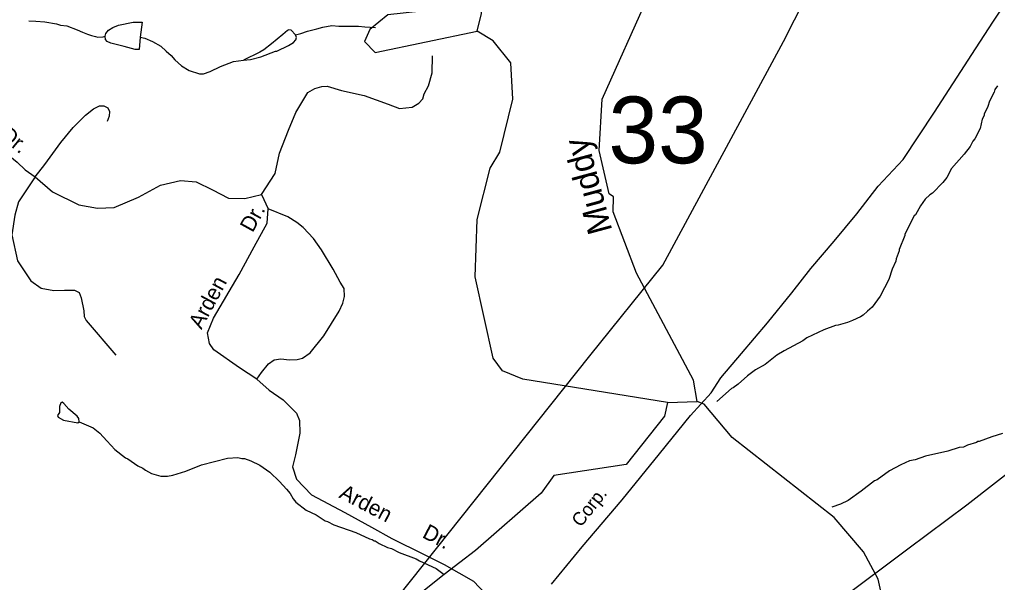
# Model space of a CAD drawing. Extents: x 1547597 to 1699558, y 810033 to 920809.
# Drawn here: x 1595166 to 1601176, y 826362 to 829821 of the extents above; entities that cross this region are included whole.
import ezdxf

# ---------------------------------------------------------------- set-up
doc = ezdxf.new("R2010")
doc.units = 0
for name, color, linetype in [('Exist Boundary Political City Limit New', 7, 'Continuous'), ('Exist Hydrographic Creek Single Shore', 7, 'Continuous'), ('Exist Hydrographic Creek Single Shore Label', 7, 'Continuous'), ('Exist Hydrographic Misc Water Feature', 7, 'Continuous'), ('Exist Hydrographic Pond Under 1500 Sq Ft', 7, 'Continuous'), ('Exist Railroad Mainline', 7, 'Continuous'), ('Exist Railroad Mainline Label', 7, 'Continuous'), ('Exist Road Non-System Type 51', 7, 'Continuous'), ('Exist Road Non-System Type 51 Label', 7, 'Continuous'), ('Exist Road Secondary Structure Standard Bridge Number Label', 7, 'Continuous'), ('Exist Utilities Electrical Transmission Line', 7, 'Continuous'), ('Map Preparation Boundary City Limit Buffer Line', 7, 'Continuous')]:
    doc.layers.add(name, color=color, linetype=linetype)

msp = doc.modelspace()

# ---------------------------------------------------------------- linework, layer by layer
at = {"layer": 'Exist Boundary Political City Limit New'}
msp.add_lwpolyline([(1595159.9, 823742.9), (1596126.5, 824626.4), (1596938.9, 825577.9), (1598671.6, 827755.3), (1599119.8, 828312.6), (1599862.2, 829685.3), (1600674.7, 831289.2), (1600128.4, 831887.3), (1599217.9, 832804.7), (1599067.4, 833015.2), (1598754.8, 833517.5), (1598535.5, 834121.7), (1598377.2, 834572.6), (1598149, 835207), (1597793.5, 835631), (1597451.9, 835864.5), (1596684.8, 836157), (1596268.5, 836512.2)], dxfattribs=at)
at = {"layer": 'Exist Hydrographic Creek Single Shore'}
msp.add_line((1599148.6, 827468.1), (1599331.6, 827474.3), dxfattribs=at)
for points in [[(1599331.6, 827474.3), (1599308.6, 827606), (1598958.6, 828263.1), (1598813.6, 828640.2), (1598815.6, 828732.1), (1598790.6, 828749.1), (1598727.6, 829016.2), (1598747.6, 829330.9), (1599031.6, 829968.6), (1599097, 830143.8), (1599212, 830246.7), (1599453.2, 830408), (1599920.6, 831033.9), (1600066.6, 831316.5), (1600092.7, 831424.3), (1600064.7, 831799.1)], [(1599148.6, 827468.1), (1598258.6, 827610.9), (1598133.6, 827662.7), (1598076.6, 827739.3), (1597966.6, 828240.5), (1597979.6, 828591.5), (1598058.6, 828908.3), (1598118.6, 829005.6), (1598197.7, 829332.2), (1598184.7, 829555.7), (1598077.6, 829689.2), (1597978.6, 829750.3)], [(1599148.6, 827468.1), (1599130.7, 827383.1), (1598893.6, 827085.9), (1598450.6, 827019.4), (1598373, 826911), (1597968.6, 826558.9), (1597775.8, 826410), (1597490.3, 826184.3), (1597347.3, 826111.7), (1596877.3, 825951.8), (1596099.6, 825773.7), (1595674.6, 825788.9), (1595550.7, 825820.9), (1595012.6, 826130.5), (1594738.6, 826218.2), (1594623.6, 826351.8), (1594518.6, 826587), (1594430.6, 826880.9), (1594384.6, 827203.6), (1594403.6, 827380.4), (1594498.6, 827654.3), (1594492.6, 827828.4), (1594348.6, 828264.6)], [(1600488.6, 826055.7), (1600482.7, 826206.8), (1600442.6, 826381.6), (1600353.6, 826550.8), (1600172.6, 826761.3), (1599545.6, 827253.3), (1599373.6, 827457), (1599331.6, 827474.3)]]:
    msp.add_lwpolyline(points, dxfattribs=at)
at = {"layer": 'Exist Hydrographic Misc Water Feature'}
for points in [[(1595223.4, 829812.1), (1595265.9, 829810.9), (1595321.9, 829806.1), (1595393.7, 829795.1), (1595417.6, 829786.8), (1595457.5, 829782.2), (1595521.1, 829757.4), (1595552.9, 829742.9), (1595584.7, 829730.4), (1595608.6, 829722.1), (1595632.5, 829715.8), (1595648.5, 829713.6), (1595680.5, 829715.1), (1595693.5, 829719)], [(1595693.5, 829719), (1595695.7, 829735.2), (1595713.1, 829755.1), (1595739, 829772.3), (1595775.4, 829786.3), (1595864.7, 829805.8), (1595920.2, 829805.6), (1595908.2, 829712.3)], [(1596862.7, 829726.5), (1596836.3, 829755), (1596820.3, 829757.2), (1596812.2, 829753.4), (1596783.9, 829729.7), (1596715.2, 829670.7), (1596666.8, 829635.4), (1596642.6, 829619.7), (1596542, 829571)], [(1596862.7, 829726.5), (1596896, 829734.2), (1596936.2, 829749.6), (1596992.4, 829764.8), (1597030.4, 829774.3), (1597086.5, 829783.5), (1597128.5, 829780.9), (1597248.4, 829781.2), (1597288.4, 829776.7), (1597353.5, 829771.1)], [(1595908.2, 829712.3), (1595900.5, 829636.7), (1595876.4, 829637), (1595810.3, 829655.6), (1595726.6, 829676.3), (1595704.9, 829686.1), (1595694.1, 829698), (1595693.5, 829719)], [(1595908.2, 829712.3), (1595936.2, 829705.6), (1595983.8, 829686.9), (1596035.4, 829658.2), (1596067, 829625.8), (1596098.6, 829599.3), (1596120.2, 829573), (1596161.7, 829536.5), (1596209.3, 829507.8), (1596273, 829486.9), (1596296.9, 829486.6), (1596337.1, 829502), (1596401.5, 829533.1), (1596481.9, 829564), (1596542, 829571)], [(1596542, 829571), (1596586, 829574.5), (1596650.1, 829591.6), (1596738.6, 829626.4), (1596746.6, 829626.3), (1596819, 829661.3), (1596849.3, 829680.8), (1596863.5, 829696.7), (1596867.7, 829710.5), (1596862.7, 829726.5)], [(1601177.1, 829414.6), (1601160.8, 829390.8), (1601156.6, 829374.9), (1601127.9, 829319.3), (1601117.4, 829287.4), (1601094.8, 829239.7), (1601094.6, 829231.8), (1601082.3, 829207.9), (1601069.6, 829152.1), (1601036.7, 829088.6), (1601024.5, 829072.8), (1601008.1, 829041), (1600971.5, 828993.5), (1600894.4, 828906.6), (1600865.6, 828851), (1600841.2, 828819.4), (1600776.3, 828754.3), (1600760.2, 828744.5), (1600731.9, 828716.9), (1600703.3, 828677.3), (1600672.7, 828621.8), (1600664.6, 828613.9), (1600607, 828502.7), (1600606.9, 828494.7), (1600571.8, 828407.2), (1600571.7, 828399.2), (1600553, 828351.5), (1600550.7, 828335.6), (1600530.1, 828287.8), (1600509.3, 828224.2), (1600455.9, 828120.9), (1600407, 828053.6), (1600376.7, 828030), (1600350.4, 828004.4), (1600334.2, 827994.7), (1600285.9, 827971.3), (1600253.8, 827959.8), (1600197.6, 827942.5), (1600181.7, 827940.8), (1600109.3, 827913.8), (1600004.7, 827865.3), (1599980.5, 827847.6), (1599865.7, 827785.2), (1599821.3, 827757.8), (1599748.6, 827700.9), (1599690.1, 827667.7), (1599639.7, 827632.4), (1599583, 827581.2), (1599552.8, 827557.7), (1599542.7, 827553.8), (1599451.9, 827473.1)], [(1595532.8, 827350), (1595529.7, 827370.5), (1595519.6, 827384.4), (1595468.7, 827426.6), (1595437.8, 827461.7), (1595427.5, 827469.3), (1595419.5, 827465.9), (1595411.8, 827443.2), (1595412.7, 827406.1), (1595399.8, 827388), (1595403.2, 827378.3), (1595436, 827360.2), (1595525.3, 827342.7), (1595532.8, 827350)], [(1595532.8, 827350), (1595619.1, 827312.5), (1595659.7, 827278.9), (1595703.7, 827232.2)], [(1595703.7, 827232.2), (1595730, 827202.9), (1595751.8, 827178.7), (1595817, 827127.8), (1595831, 827121.6), (1595892.4, 827078.8), (1595924.2, 827064.3), (1595939.9, 827052.1), (1595977.7, 827031.6), (1596035.4, 827014.8), (1596075.4, 827014.2), (1596107.5, 827021.8), (1596187.8, 827046.7), (1596284.2, 827085.3), (1596444.7, 827125), (1596508.7, 827130.2), (1596532.5, 827123.8), (1596548.5, 827123.6), (1596588.3, 827109.1), (1596644, 827082.3), (1596705.3, 827039.4), (1596764.6, 826982.6), (1596807.8, 826936), (1596829.5, 826907.7), (1596847, 826875.5), (1596864.7, 826855.3), (1596928, 826806.4), (1596989.6, 826777.5), (1597045.1, 826740.8), (1597059, 826736.6), (1597098.7, 826716), (1597233.9, 826668.1), (1597317.4, 826631), (1597333.4, 826626.8), (1597345.3, 826618.6), (1597351.2, 826618.5), (1597377, 826602.2), (1597428.6, 826577.5), (1597452.5, 826571.2), (1597500.2, 826546.5), (1597603.5, 826507.1), (1597623.3, 826494.8), (1597726.7, 826447.4), (1597775.8, 826410)], [(1601207.9, 827276.6), (1601141.7, 827257.6), (1601063.4, 827228.7), (1601055.4, 827228.8), (1601047.3, 827222.9), (1600991.1, 827205.7), (1600967, 827194), (1600941, 827190.4), (1600870.6, 827169.3), (1600734.3, 827137.2), (1600670.1, 827116.2), (1600635.9, 827108.6), (1600581.7, 827085.4), (1600513.2, 827048.4), (1600436.5, 826993.5), (1600420.4, 826985.7), (1600339.6, 826922.8), (1600258.9, 826866), (1600210.6, 826842.6), (1600158.8, 826824.4)]]:
    msp.add_lwpolyline(points, dxfattribs=at)
at = {"layer": 'Exist Hydrographic Pond Under 1500 Sq Ft'}
msp.add_lwpolyline([(1597978.6, 829750.3), (1598004.6, 829858.1), (1597989.6, 830009.4), (1597800.6, 830210.2), (1597802.6, 830318.5), (1597670.6, 830423), (1597561.6, 830389), (1597567.7, 830247.8), (1597632.7, 830095.4), (1597689.7, 830028.6), (1597688.6, 829903.9), (1597637.6, 829872.1), (1597429.7, 829850.1), (1597319.6, 829760.4), (1597285.6, 829685.5), (1597351.6, 829618.5), (1597978.6, 829750.3)], dxfattribs=at)
at = {"layer": 'Exist Railroad Mainline'}
msp.add_lwpolyline([(1598434.5, 826352.6), (1598624.1, 826581.4), (1598869.8, 826869.5), (1599098.5, 827152.5), (1599289.1, 827387.8), (1599416.8, 827528.1), (1599475.8, 827619.1), (1599603.8, 827769.4), (1599763.9, 827957.3), (1599912.1, 828141.4), (1600030, 828291.9), (1600171.9, 828459.9), (1600311.9, 828626.2), (1600444, 828796.4), (1600596.3, 828961.5), (1600789.9, 829251.6), (1601019.1, 829606.8), (1601147.7, 829804.9), (1601289.9, 830019.8)], dxfattribs=at)
at = {"layer": 'Exist Road Non-System Type 51'}
for points in [[(1596652.6, 828745.3), (1596736.6, 828874), (1596764.2, 828999.5), (1596818.3, 829141.5), (1596863.5, 829250.8), (1596939, 829371.8), (1596981.8, 829397.9), (1597023.2, 829409.5), (1597057, 829411), (1597144.2, 829385.8), (1597284.3, 829354.9), (1597431.5, 829301.1), (1597502.2, 829274.4), (1597578.9, 829282), (1597619.5, 829307.5), (1597645.8, 829332.8), (1597652.6, 829364.7), (1597679.7, 829412.9), (1597701.7, 829494), (1597703.2, 829597.8)], [(1595262.2, 828853.5), (1595321.2, 828930.7), (1595420.8, 829065.4), (1595495.9, 829158.3), (1595570.9, 829233.4), (1595621.3, 829272.6), (1595657.5, 829290.1), (1595683.5, 829289.8), (1595709.3, 829277.6), (1595719, 829255.4), (1595716.7, 829227.5), (1595704.2, 829193.7)], [(1594046.2, 829198.9), (1594144.1, 829201.5), (1594309.9, 829195.6), (1594497.5, 829183.2), (1594637.1, 829169.3), (1594762.7, 829147.8), (1594890, 829108.2), (1594993.3, 829060.8), (1595074.5, 829007.8), (1595151.6, 828945), (1595200.9, 828898.3), (1595262.2, 828853.5)], [(1595262.2, 828853.5), (1595160.4, 828700.1), (1595136.4, 828618.8), (1595118.3, 828498.4), (1595154.4, 828338.8), (1595235.7, 828215.4), (1595298.8, 828170.2), (1595377, 828155.2), (1595443.2, 828158.2), (1595503.4, 828158.2), (1595533.5, 828143.1), (1595545.5, 828110), (1595560.5, 828031.7), (1595563.6, 827995.6), (1595575.6, 827971.5), (1595759.1, 827757.8)], [(1595262.2, 828853.5), (1595368, 828763.3), (1595530.5, 828682), (1595644.8, 828661), (1595747.1, 828667), (1595897.5, 828730.2), (1596032.8, 828802.5), (1596156.2, 828832.6), (1596252.5, 828823.5), (1596351.7, 828775.4), (1596451, 828724.2), (1596550.3, 828721.2), (1596652.6, 828745.3)], [(1596652.6, 828745.3), (1596694.7, 828658)], [(1596624.4, 827610.7), (1596517.5, 827680.2), (1596361.1, 827792), (1596333.7, 827830.4), (1596322.3, 827896.2), (1596357.5, 827986.2), (1596515.1, 828254.7), (1596609, 828424.5), (1596688.8, 828569.4), (1596694.7, 828658)], [(1596624.4, 827610.7), (1596653, 827652.4), (1596695.5, 827705.8), (1596731.8, 827729.4), (1596772, 827736.8), (1596825.7, 827730.1), (1596871.7, 827731.6), (1596905.7, 827741.1), (1596952.2, 827772.6), (1597037.4, 827877.3), (1597131.3, 828028.1), (1597153.9, 828077.7), (1597162.6, 828119.5), (1597161.1, 828167.6), (1597137.7, 828207.9), (1597094.7, 828286.4), (1597022.3, 828405.3), (1596973.3, 828475.8), (1596910.2, 828542.7), (1596870.8, 828573.1), (1596815.3, 828607.8), (1596694.7, 828658)], [(1596624.4, 827610.7), (1596699.4, 827543.8), (1596786.8, 827483.8), (1596868, 827402.5), (1596886.1, 827357.3), (1596889.1, 827279), (1596862, 827146.6), (1596843.2, 827072.2), (1596868, 826996), (1596961.3, 826899.7), (1597165.9, 826791.3), (1597328.3, 826701), (1597454.7, 826631.7), (1597649.4, 826536.3), (1597775.7, 826473), (1597956.2, 826370.7), (1598067.5, 826253.3), (1598159, 826144.6), (1598202.5, 826108.1), (1598248, 826093.7)]]:
    msp.add_lwpolyline(points, dxfattribs=at)
at = {"layer": 'Exist Utilities Electrical Transmission Line'}
msp.add_lwpolyline([(1600209.6, 826257.5), (1600626.2, 826568.8), (1600988.2, 826839.2), (1601358.3, 827127.3)], dxfattribs=at)
at = {"layer": 'Map Preparation Boundary City Limit Buffer Line'}
msp.add_lwpolyline([(1595159.9, 823742.9), (1596126.5, 824626.4), (1596938.9, 825577.9), (1598671.6, 827755.3), (1599119.8, 828312.6), (1599862.2, 829685.3), (1600674.7, 831289.2), (1600128.4, 831887.3), (1599217.9, 832804.7), (1599067.4, 833015.2), (1598754.8, 833517.5), (1598535.5, 834121.7), (1598377.2, 834572.6), (1598149, 835207), (1597793.5, 835631), (1597451.9, 835864.5), (1596684.8, 836157), (1596268.5, 836512.2)], dxfattribs=at)

# ---------------------------------------------------------------- texts
at = {"layer": 'Exist Hydrographic Creek Single Shore Label'}
msp.add_text('Muddy', height=150, rotation=105.10668, dxfattribs=at).set_placement((1598810.2, 828525.3))
at = {"layer": 'Exist Railroad Mainline Label'}
msp.add_text('Corp.', height=82.02, rotation=51.67395, dxfattribs=at).set_placement((1598615.9, 826697.2))
at = {"layer": 'Exist Road Non-System Type 51 Label'}
for s, rotation, p in [('Dr.', 320.86041, (1595040.9, 829098.5)), ('Dr.', 61.15759, (1596598.5, 828507.4)), ('Arden', 61.65773, (1596283.6, 827912.5)), ('Arden', 332.27238, (1597124, 826886.2)), ('Dr.', 332.3045, (1597635.5, 826641.5))]:
    msp.add_text(s, height=95, rotation=rotation, dxfattribs=at).set_placement(p)
at = {"layer": 'Exist Road Secondary Structure Standard Bridge Number Label'}
msp.add_text('33', height=410.1, dxfattribs=at).set_placement((1598785.8, 828937.5))

doc.saveas('drawing.dxf')
